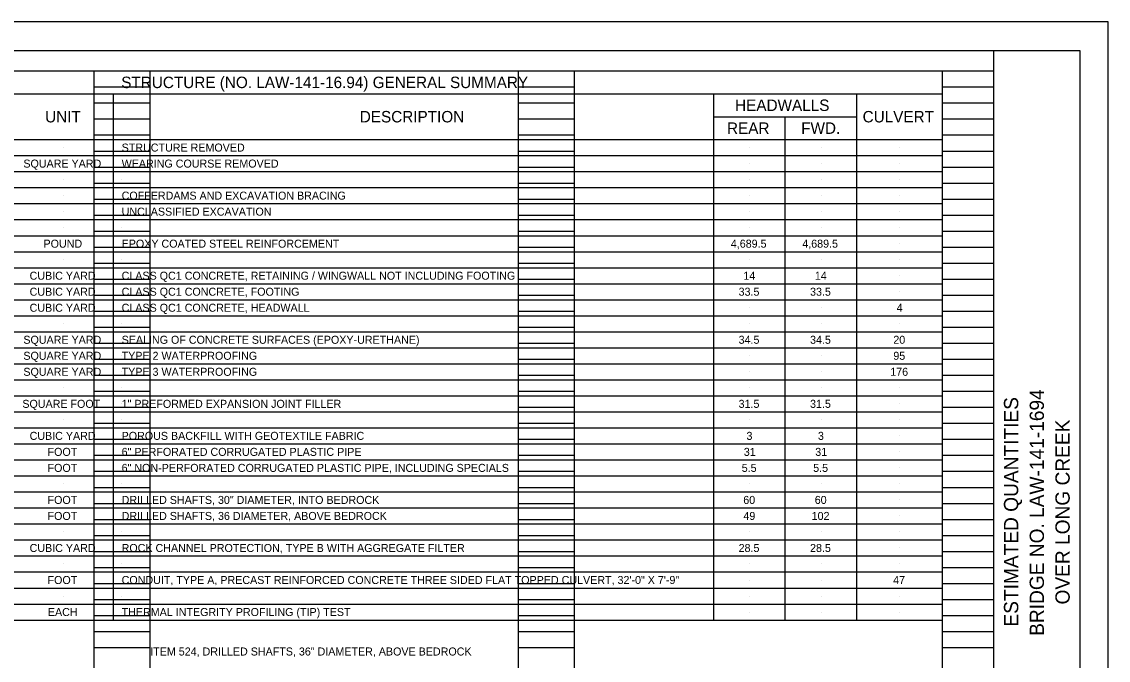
# Model space of a CAD drawing. Extents: x 0 to 34, y 0 to 22.
# Drawn here: x 14.99 to 34, y 10.84 to 22 of the extents above; entities that cross this region are included whole.
import ezdxf

# ---------------------------------------------------------------- set-up
doc = ezdxf.new("R2010")
doc.units = 0
for name, color, linetype in [('BR_P_Gen_Text', 7, 'Continuous'), ('SC_Scratch1', 7, 'Continuous'), ('SC_Scratch2', 7, 'Continuous'), ('SH_Border', 7, 'Continuous'), ('SH_Cut_Line', 7, 'Continuous'), ('SH_Data', 7, 'Continuous')]:
    doc.layers.add(name, color=color, linetype=linetype)

msp = doc.modelspace()

# ---------------------------------------------------------------- linework, layer by layer
at = {"layer": 'SC_Scratch1'}
for p, q in [((15.725, 19.8), (15.725, 19.8)), ((16.74, 19.8), (16.74, 19.8)), ((27.725, 19.8), (27.725, 19.8)), ((28.975, 19.8), (28.975, 19.8)), ((30.35, 19.8), (30.35, 19.8)), ((15.725, 19.52), (15.725, 19.52)), ((16.74, 19.52), (16.74, 19.52)), ((27.725, 19.52), (27.725, 19.52)), ((28.975, 19.52), (28.975, 19.52)), ((30.35, 19.52), (30.35, 19.52)), ((15.725, 19.24), (15.725, 19.24)), ((16.74, 19.24), (16.74, 19.24)), ((27.725, 19.24), (27.725, 19.24)), ((28.975, 19.24), (28.975, 19.24)), ((30.35, 19.24), (30.35, 19.24)), ((15.725, 18.96), (15.725, 18.96)), ((16.74, 18.96), (16.74, 18.96)), ((27.725, 18.96), (27.725, 18.96)), ((28.975, 18.96), (28.975, 18.96)), ((30.35, 18.96), (30.35, 18.96)), ((15.725, 18.68), (15.725, 18.68)), ((16.74, 18.68), (16.74, 18.68)), ((27.725, 18.68), (27.725, 18.68)), ((28.975, 18.68), (28.975, 18.68)), ((30.35, 18.68), (30.35, 18.68)), ((15.725, 18.4), (15.725, 18.4)), ((16.74, 18.4), (16.74, 18.4)), ((27.725, 18.4), (27.725, 18.4)), ((28.975, 18.4), (28.975, 18.4)), ((30.35, 18.4), (30.35, 18.4)), ((15.725, 18.12), (15.725, 18.12)), ((16.74, 18.12), (16.74, 18.12)), ((27.725, 18.12), (27.725, 18.12)), ((28.975, 18.12), (28.975, 18.12)), ((30.35, 18.12), (30.35, 18.12)), ((15.725, 17.84), (15.725, 17.84)), ((16.74, 17.84), (16.74, 17.84)), ((27.725, 17.84), (27.725, 17.84)), ((28.975, 17.84), (28.975, 17.84)), ((30.35, 17.84), (30.35, 17.84)), ((15.725, 17.56), (15.725, 17.56)), ((16.74, 17.56), (16.74, 17.56)), ((27.725, 17.56), (27.725, 17.56)), ((28.975, 17.56), (28.975, 17.56)), ((30.35, 17.56), (30.35, 17.56)), ((15.725, 17.28), (15.725, 17.28)), ((16.74, 17.28), (16.74, 17.28)), ((27.725, 17.28), (27.725, 17.28)), ((28.975, 17.28), (28.975, 17.28)), ((30.35, 17.28), (30.35, 17.28)), ((15.725, 17), (15.725, 17)), ((16.74, 17), (16.74, 17)), ((27.725, 17), (27.725, 17)), ((28.975, 17), (28.975, 17)), ((30.35, 17), (30.35, 17)), ((15.725, 16.72), (15.725, 16.72)), ((16.74, 16.72), (16.74, 16.72)), ((27.725, 16.72), (27.725, 16.72)), ((28.975, 16.72), (28.975, 16.72)), ((30.35, 16.72), (30.35, 16.72)), ((15.725, 16.44), (15.725, 16.44)), ((16.74, 16.44), (16.74, 16.44)), ((27.725, 16.44), (27.725, 16.44)), ((28.975, 16.44), (28.975, 16.44)), ((30.35, 16.44), (30.35, 16.44)), ((15.725, 16.16), (15.725, 16.16)), ((16.74, 16.16), (16.74, 16.16)), ((27.725, 16.16), (27.725, 16.16)), ((28.975, 16.16), (28.975, 16.16)), ((30.35, 16.16), (30.35, 16.16)), ((15.725, 15.88), (15.725, 15.88)), ((16.74, 15.88), (16.74, 15.88)), ((27.725, 15.88), (27.725, 15.88)), ((28.975, 15.88), (28.975, 15.88)), ((30.35, 15.88), (30.35, 15.88)), ((15.725, 15.6), (15.725, 15.6)), ((16.74, 15.6), (16.74, 15.6)), ((27.725, 15.6), (27.725, 15.6)), ((28.975, 15.6), (28.975, 15.6)), ((30.35, 15.6), (30.35, 15.6)), ((15.725, 15.32), (15.725, 15.32)), ((16.74, 15.32), (16.74, 15.32)), ((27.725, 15.32), (27.725, 15.32)), ((28.975, 15.32), (28.975, 15.32)), ((30.35, 15.32), (30.35, 15.32)), ((15.725, 15.04), (15.725, 15.04)), ((16.74, 15.04), (16.74, 15.04)), ((27.725, 15.04), (27.725, 15.04)), ((28.975, 15.04), (28.975, 15.04)), ((30.35, 15.04), (30.35, 15.04)), ((15.725, 14.76), (15.725, 14.76)), ((16.74, 14.76), (16.74, 14.76)), ((27.725, 14.76), (27.725, 14.76)), ((28.975, 14.76), (28.975, 14.76)), ((30.35, 14.76), (30.35, 14.76)), ((15.725, 14.48), (15.725, 14.48)), ((16.74, 14.48), (16.74, 14.48)), ((27.725, 14.48), (27.725, 14.48)), ((28.975, 14.48), (28.975, 14.48)), ((30.35, 14.48), (30.35, 14.48)), ((15.725, 14.2), (15.725, 14.2)), ((16.74, 14.2), (16.74, 14.2)), ((27.725, 14.2), (27.725, 14.2)), ((28.975, 14.2), (28.975, 14.2)), ((30.35, 14.2), (30.35, 14.2)), ((15.725, 13.92), (15.725, 13.92)), ((16.74, 13.92), (16.74, 13.92)), ((27.725, 13.92), (27.725, 13.92)), ((28.975, 13.92), (28.975, 13.92)), ((30.35, 13.92), (30.35, 13.92)), ((15.725, 13.64), (15.725, 13.64)), ((16.74, 13.64), (16.74, 13.64)), ((27.725, 13.64), (27.725, 13.64)), ((28.975, 13.64), (28.975, 13.64)), ((30.35, 13.64), (30.35, 13.64)), ((15.725, 13.36), (15.725, 13.36)), ((16.74, 13.36), (16.74, 13.36)), ((27.725, 13.36), (27.725, 13.36)), ((28.975, 13.36), (28.975, 13.36)), ((30.35, 13.36), (30.35, 13.36)), ((15.725, 13.08), (15.725, 13.08)), ((16.74, 13.08), (16.74, 13.08)), ((27.725, 13.08), (27.725, 13.08)), ((28.975, 13.08), (28.975, 13.08)), ((30.35, 13.08), (30.35, 13.08)), ((15.725, 12.8), (15.725, 12.8)), ((16.74, 12.8), (16.74, 12.8)), ((27.725, 12.8), (27.725, 12.8)), ((28.975, 12.8), (28.975, 12.8)), ((30.35, 12.8), (30.35, 12.8)), ((15.725, 12.52), (15.725, 12.52)), ((16.74, 12.52), (16.74, 12.52)), ((27.725, 12.52), (27.725, 12.52)), ((28.975, 12.52), (28.975, 12.52)), ((30.35, 12.52), (30.35, 12.52)), ((15.725, 12.24), (15.725, 12.24)), ((16.74, 12.24), (16.74, 12.24)), ((27.725, 12.24), (27.725, 12.24)), ((28.975, 12.24), (28.975, 12.24)), ((30.35, 12.24), (30.35, 12.24)), ((15.725, 11.96), (15.725, 11.96)), ((16.74, 11.96), (16.74, 11.96)), ((27.725, 11.96), (27.725, 11.96)), ((28.975, 11.96), (28.975, 11.96)), ((30.35, 11.96), (30.35, 11.96)), ((15.725, 11.68), (15.725, 11.68)), ((16.74, 11.68), (16.74, 11.68)), ((27.725, 11.68), (27.725, 11.68)), ((28.975, 11.68), (28.975, 11.68)), ((30.35, 11.68), (30.35, 11.68))]:
    msp.add_line(p, q, dxfattribs=at)
at = {"layer": 'SC_Scratch2'}
for p, q in [((16.26, 0.98), (16.26, 21.14)), ((16.26, 21.14), (17.24, 21.14)), ((17.24, 0.98), (17.24, 21.14)), ((23.68, 0.98), (23.68, 21.14)), ((23.68, 21.14), (24.66, 21.14)), ((24.66, 0.98), (24.66, 21.14)), ((31.1, 0.98), (31.1, 21.14)), ((31.1, 21.14), (32, 21.14)), ((32, 0.98), (32, 21.14)), ((16.26, 20.86), (17.24, 20.86)), ((23.68, 20.86), (24.66, 20.86)), ((31.1, 20.86), (32, 20.86)), ((16.26, 20.58), (17.24, 20.58)), ((23.68, 20.58), (24.66, 20.58)), ((31.1, 20.58), (32, 20.58)), ((16.26, 20.3), (17.24, 20.3)), ((23.68, 20.3), (24.66, 20.3)), ((31.1, 20.3), (32, 20.3)), ((16.26, 20.02), (17.24, 20.02)), ((23.68, 20.02), (24.66, 20.02)), ((31.1, 20.02), (32, 20.02)), ((16.26, 19.74), (17.24, 19.74)), ((23.68, 19.74), (24.66, 19.74)), ((31.1, 19.74), (32, 19.74)), ((16.26, 19.46), (17.24, 19.46)), ((23.68, 19.46), (24.66, 19.46)), ((31.1, 19.46), (32, 19.46)), ((16.26, 19.18), (17.24, 19.18)), ((23.68, 19.18), (24.66, 19.18)), ((31.1, 19.18), (32, 19.18)), ((16.26, 18.9), (17.24, 18.9)), ((23.68, 18.9), (24.66, 18.9)), ((31.1, 18.9), (32, 18.9)), ((16.26, 18.62), (17.24, 18.62)), ((23.68, 18.62), (24.66, 18.62)), ((31.1, 18.62), (32, 18.62)), ((16.26, 18.34), (17.24, 18.34)), ((23.68, 18.34), (24.66, 18.34)), ((31.1, 18.34), (32, 18.34)), ((16.26, 18.06), (17.24, 18.06)), ((23.68, 18.06), (24.66, 18.06)), ((31.1, 18.06), (32, 18.06)), ((16.26, 17.78), (17.24, 17.78)), ((23.68, 17.78), (24.66, 17.78)), ((31.1, 17.78), (32, 17.78)), ((16.26, 17.5), (17.24, 17.5)), ((23.68, 17.5), (24.66, 17.5)), ((31.1, 17.5), (32, 17.5)), ((16.26, 17.22), (17.24, 17.22)), ((23.68, 17.22), (24.66, 17.22)), ((31.1, 17.22), (32, 17.22)), ((16.26, 16.94), (17.24, 16.94)), ((23.68, 16.94), (24.66, 16.94)), ((31.1, 16.94), (32, 16.94)), ((16.26, 16.66), (17.24, 16.66)), ((23.68, 16.66), (24.66, 16.66)), ((31.1, 16.66), (32, 16.66)), ((16.26, 16.38), (17.24, 16.38)), ((23.68, 16.38), (24.66, 16.38)), ((31.1, 16.38), (32, 16.38)), ((16.26, 16.1), (17.24, 16.1)), ((23.68, 16.1), (24.66, 16.1)), ((31.1, 16.1), (32, 16.1)), ((16.26, 15.82), (17.24, 15.82)), ((23.68, 15.82), (24.66, 15.82)), ((31.1, 15.82), (32, 15.82)), ((16.26, 15.54), (17.24, 15.54)), ((23.68, 15.54), (24.66, 15.54)), ((31.1, 15.54), (32, 15.54)), ((16.26, 15.26), (17.24, 15.26)), ((23.68, 15.26), (24.66, 15.26)), ((31.1, 15.26), (32, 15.26)), ((16.26, 14.98), (17.24, 14.98)), ((23.68, 14.98), (24.66, 14.98)), ((31.1, 14.98), (32, 14.98)), ((16.26, 14.7), (17.24, 14.7)), ((23.68, 14.7), (24.66, 14.7)), ((31.1, 14.7), (32, 14.7)), ((16.26, 14.42), (17.24, 14.42)), ((23.68, 14.42), (24.66, 14.42)), ((31.1, 14.42), (32, 14.42)), ((16.26, 14.14), (17.24, 14.14)), ((23.68, 14.14), (24.66, 14.14)), ((31.1, 14.14), (32, 14.14)), ((16.26, 13.86), (17.24, 13.86)), ((23.68, 13.86), (24.66, 13.86)), ((31.1, 13.86), (32, 13.86)), ((16.26, 13.58), (17.24, 13.58)), ((23.68, 13.58), (24.66, 13.58)), ((31.1, 13.58), (32, 13.58)), ((16.26, 13.3), (17.24, 13.3)), ((23.68, 13.3), (24.66, 13.3)), ((31.1, 13.3), (32, 13.3)), ((16.26, 13.02), (17.24, 13.02)), ((23.68, 13.02), (24.66, 13.02)), ((31.1, 13.02), (32, 13.02)), ((16.26, 12.74), (17.24, 12.74)), ((23.68, 12.74), (24.66, 12.74)), ((31.1, 12.74), (32, 12.74)), ((16.26, 12.46), (17.24, 12.46)), ((23.68, 12.46), (24.66, 12.46)), ((31.1, 12.46), (32, 12.46)), ((16.26, 12.18), (17.24, 12.18)), ((23.68, 12.18), (24.66, 12.18)), ((31.1, 12.18), (32, 12.18)), ((16.26, 11.9), (17.24, 11.9)), ((23.68, 11.9), (24.66, 11.9)), ((31.1, 11.9), (32, 11.9)), ((16.26, 11.62), (17.24, 11.62)), ((23.68, 11.62), (24.66, 11.62)), ((31.1, 11.62), (32, 11.62)), ((16.26, 11.34), (17.24, 11.34)), ((23.68, 11.34), (24.66, 11.34)), ((31.1, 11.34), (32, 11.34)), ((16.26, 11.06), (17.24, 11.06)), ((23.68, 11.06), (24.66, 11.06)), ((31.1, 11.06), (32, 11.06))]:
    msp.add_line(p, q, dxfattribs=at)
at = {"layer": 'SH_Border'}
msp.add_line((32, 0.5), (32, 21.5), dxfattribs=at)
msp.add_lwpolyline([(1.5, 21.5), (33.5, 21.5), (33.5, 0.5), (1.5, 0.5)], close=True, dxfattribs=at)
at = {"layer": 'SH_Cut_Line'}
msp.add_lwpolyline([(0, 0), (34, 0), (34, 22), (0, 22)], close=True, dxfattribs=at)
at = {"layer": 'SH_Data'}
for p, q in [((9.85, 21.14), (31.1, 21.14)), ((31.1, 11.54), (31.1, 21.14)), ((9.85, 20.74), (31.1, 20.74)), ((16.6, 11.54), (16.6, 20.74)), ((27.1, 11.54), (27.1, 20.74)), ((29.6, 11.54), (29.6, 20.74)), ((27.1, 20.34), (29.6, 20.34)), ((28.35, 11.54), (28.35, 20.34)), ((9.85, 19.94), (31.1, 19.94)), ((9.85, 19.66), (31.1, 19.66)), ((9.85, 19.38), (31.1, 19.38)), ((9.85, 19.1), (31.1, 19.1)), ((9.85, 18.82), (31.1, 18.82)), ((9.85, 18.54), (31.1, 18.54)), ((9.85, 18.26), (31.1, 18.26)), ((9.85, 17.98), (31.1, 17.98)), ((9.85, 17.7), (31.1, 17.7)), ((9.85, 17.42), (31.1, 17.42)), ((9.85, 17.14), (31.1, 17.14)), ((9.85, 16.86), (31.1, 16.86)), ((9.85, 16.58), (31.1, 16.58)), ((9.85, 16.3), (31.1, 16.3)), ((9.85, 16.02), (31.1, 16.02)), ((9.85, 15.74), (31.1, 15.74)), ((9.85, 15.46), (31.1, 15.46)), ((9.85, 15.18), (31.1, 15.18)), ((9.85, 14.9), (31.1, 14.9)), ((9.85, 14.62), (31.1, 14.62)), ((9.85, 14.34), (31.1, 14.34)), ((9.85, 14.06), (31.1, 14.06)), ((9.85, 13.78), (31.1, 13.78)), ((9.85, 13.5), (31.1, 13.5)), ((9.85, 13.22), (31.1, 13.22)), ((9.85, 12.94), (31.1, 12.94)), ((9.85, 12.66), (31.1, 12.66)), ((9.85, 12.38), (31.1, 12.38)), ((9.85, 12.1), (31.1, 12.1)), ((9.85, 11.82), (31.1, 11.82)), ((9.85, 11.54), (31.1, 11.54))]:
    msp.add_line(p, q, dxfattribs=at)

# ---------------------------------------------------------------- texts
at = {"layer": 'BR_P_Gen_Text'}
for s, p in [('STRUCTURE REMOVED', (16.74, 19.73)), ('SQUARE YARD', (15.021, 19.45)), ('WEARING COURSE REMOVED', (16.74, 19.45)), ('COFFERDAMS AND EXCAVATION BRACING', (16.74, 18.89)), ('UNCLASSIFIED EXCAVATION', (16.74, 18.61)), ('POUND', (15.373, 18.05)), ('EPOXY COATED STEEL REINFORCEMENT', (16.74, 18.05)), ('4,689.5', (27.397, 18.05)), ('4,689.5', (28.647, 18.05)), ('CUBIC YARD', (15.13, 17.49)), ('CLASS QC1 CONCRETE, RETAINING / WINGWALL NOT INCLUDING FOOTING', (16.74, 17.49)), ('14', (27.617, 17.49)), ('14', (28.867, 17.49)), ('CUBIC YARD', (15.13, 17.21)), ('CLASS QC1 CONCRETE, FOOTING', (16.74, 17.21)), ('33.5', (27.533, 17.21)), ('33.5', (28.783, 17.21)), ('CUBIC YARD', (15.13, 16.93)), ('CLASS QC1 CONCRETE, HEADWALL', (16.74, 16.93)), ('4', (30.297, 16.93)), ('SQUARE YARD', (15.021, 16.37)), ('SEALING OF CONCRETE SURFACES (EPOXY-URETHANE)', (16.74, 16.37)), ('34.5', (27.533, 16.37)), ('34.5', (28.783, 16.37)), ('20', (30.24, 16.37)), ('SQUARE YARD', (15.021, 16.09)), ('TYPE 2 WATERPROOFING', (16.74, 16.09)), ('95', (30.24, 16.09)), ('SQUARE YARD', (15.021, 15.81)), ('TYPE 3 WATERPROOFING', (16.74, 15.81)), ('176', (30.186, 15.81)), ('SQUARE FOOT', (15.003, 15.25)), ('1" PREFORMED EXPANSION JOINT FILLER', (16.74, 15.25)), ('31.5', (27.533, 15.25)), ('31.5', (28.783, 15.25)), ('CUBIC YARD', (15.13, 14.69)), ('POROUS BACKFILL WITH GEOTEXTILE FABRIC', (16.74, 14.69)), ('3', (27.671, 14.69)), ('3', (28.921, 14.69)), ('FOOT', (15.444, 14.41)), ('6" PERFORATED CORRUGATED PLASTIC PIPE', (16.74, 14.41)), ('31', (27.624, 14.41)), ('31', (28.874, 14.41)), ('FOOT', (15.444, 14.13)), ('6" NON-PERFORATED CORRUGATED PLASTIC PIPE, INCLUDING SPECIALS', (16.74, 14.13)), ('5.5', (27.588, 14.13)), ('5.5', (28.838, 14.13)), ('FOOT', (15.444, 13.57)), ('DRILLED SHAFTS, 30" DIAMETER, INTO BEDROCK', (16.74, 13.57)), ('60', (27.615, 13.57)), ('60', (28.865, 13.57)), ('FOOT', (15.444, 13.29)), ('DRILLED SHAFTS, 36 DIAMETER, ABOVE BEDROCK', (16.74, 13.29)), ('49', (27.617, 13.29)), ('102', (28.811, 13.29)), ('CUBIC YARD', (15.13, 12.73)), ('ROCK CHANNEL PROTECTION, TYPE B WITH AGGREGATE FILTER', (16.74, 12.73)), ('28.5', (27.533, 12.73)), ('28.5', (28.783, 12.73)), ('FOOT', (15.444, 12.17)), ('CONDUIT, TYPE A, PRECAST REINFORCED CONCRETE THREE SIDED FLAT TOPPED CULVERT, 32\'-0" X 7\'-9"', (16.74, 12.17)), ('47', (30.237, 12.17)), ('EACH', (15.45, 11.61)), ('THERMAL INTEGRITY PROFILING (TIP) TEST', (16.74, 11.61)), ('ITEM 524, DRILLED SHAFTS, 36" DIAMETER, ABOVE BEDROCK', (17.24, 10.92))]:
    msp.add_text(s, height=0.14, dxfattribs=at).set_placement(p)
at = {"layer": 'SH_Data'}
for s, height, rotation, p in [('STRUCTURE (NO. LAW-141-16.94) GENERAL SUMMARY', 0.2, 360, (16.733, 20.84)), ('HEADWALLS', 0.2, 360, (27.472, 20.44)), ('UNIT', 0.2, 360, (15.402, 20.24)), ('DESCRIPTION', 0.2, 360, (20.906, 20.24)), ('CULVERT', 0.2, 360, (29.703, 20.24)), ('REAR', 0.2, 360, (27.33, 20.04)), ('FWD.', 0.2, 360, (28.628, 20.04)), ('ESTIMATED QUANTITIES', 0.25, 90, (32.425, 11.426)), ('BRIDGE NO. LAW-141-1694', 0.25, 90, (32.875, 11.264)), ('OVER LONG CREEK', 0.25, 90, (33.325, 11.812))]:
    msp.add_text(s, height=height, rotation=rotation, dxfattribs=at).set_placement(p)

doc.saveas('drawing.dxf')
